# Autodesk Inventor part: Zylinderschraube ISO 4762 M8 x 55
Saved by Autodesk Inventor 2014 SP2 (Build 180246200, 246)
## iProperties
Created: 2015-07
Part Number: Zylinderschraube ISO 4762 M8 x 55
Material: Generisch
Document SubType Name: Modeling
Designer: e_krauts
Density: 1 g/cm^3
Appearance: Vorgabe
Author: e_krauts
Sending System: SolidWorks 2011
Last Author: e_boekem
Sachnummer: ISO 4762 M8x55
Einheit: Stck.
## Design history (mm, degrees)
node "Zylinderschraube ISO 4762 M8 x 55.ipt1"
node "Hex"
node "Basis1"
